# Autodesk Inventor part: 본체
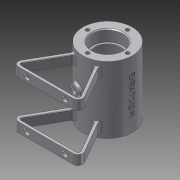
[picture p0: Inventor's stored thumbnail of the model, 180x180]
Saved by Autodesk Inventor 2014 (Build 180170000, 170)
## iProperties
Created: 2016-03
Part Number: 본체
Material: Aluminum 6061
Document SubType Name: Modeling
Designer: user
Density: 2.71 g/cm^3
Appearance: Aluminum - Flat
Mass: 209.602 g
Surface Area: 327.231 cm^2
Volume: 77.3441 cm^3
Author: user
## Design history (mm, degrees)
sketch "Sketch1"
  geometry: C1 r 26 at (0, 0); 1 further point
  constraints: 1 centre point, 1 coincident
  dimensions: "d0" = 52 diameter of C1
extrude "Extrusion1" new body sketch "Sketch1" distance "d1" = 35; taper "d2" = 0 deg
sketch "Sketch2"
  geometry: 4 further points
hole "Hole1" sketch "Sketch2" at (0, 21), (-21, 0), (0, -21), (21, 0) diameter "d5" = 4; stored, may be unused: countersink angle "d9" = 82 deg, drill point angle "d11" = 118 deg; dims "d6" = 5.984, "d7" = 3.023, "d8" = 2, "d10" = 8
sketch "Sketch3"
  geometry: C1 r 26 at (0, 0) reference; C2 r 16 at (0, 0)
  constraints: 1 centre point, 1 coincident
  dimensions: "d12" = 32 diameter of C2
extrude "Extrusion2" cut sketch "Sketch3" distance "d13" = 12; taper "d14" = 0 deg
sketch "Sketch4"
  geometry: C1 r 16 at (0, 0) reference; C2 r 14 at (0, 0)
  constraints: 1 centre point, 1 coincident
  dimensions: "d15" = 28 diameter of C2
extrude "Extrusion3" cut sketch "Sketch4" distance "d16" = 2; taper "d17" = 0 deg
sketch "Sketch5"
  geometry: C1 r 26 at (0, 0) reference; C2 r 21 at (0, 0)
  constraints: 1 centre point, 1 coincident
  dimensions: "d18" = 42 diameter of C2
extrude "Extrusion4" cut sketch "Sketch5" distance "d19" = 21; taper "d20" = 0 deg
fillet "Fillet1" dims "d21" = 0.3
workplane "Work Plane1"
sketch "Sketch6"
  geometry: L1 (13, -22.517)-(33.198, -57.5); L2 (28.868, -65)-(-28.868, -65); L3 (-33.198, -57.5)-(-13, -22.517); L4 (-28.868, -62)-(28.868, -62); L5 (30.6, -59)-(10.315, -23.866); L6 (-10.315, -23.866)-(-30.6, -59); A1 r 5 centre (28.868, -60) between (28.868, -65) and (33.198, -57.5); A2 r 5 centre (-28.868, -60) between (-33.198, -57.5) and (-28.868, -65); A3 r 2 centre (28.868, -60) between (28.868, -62) and (30.6, -59); A4 r 2 centre (-28.868, -60) between (-30.6, -59) and (-28.868, -62); A5 r 26 centre (0, 0) between (-13, -22.517) and (-10.315, -23.866); A6 r 26 centre (0, 0) between (10.315, -23.866) and (13, -22.517); 1 further point
  constraints: 12 end point, 12 point on circle, 6 centre point, 4 tangent, 1 coincident, 1 equal radius, 1 horizontal, 1 other
  dimensions: "d23" = 65 distance from line of L2 point (0, 0); "d24" = 60 deg angle of L2 L1; "d25" = 60 deg angle of L2 L3; "d26" = 5 radius of A1; "d27" = 3 distance between parallel lines of L2 L4
extrude "Extrusion5" join sketch "Sketch6" distance "d29" = 10; taper "d30" = 0 deg
sketch "Sketch7"
  geometry: L1 (57.735, 0)-(57.735, -10) reference; L2 (-20.076, -5)-(63.87, -5); L3 (28.868, 5.708)-(28.868, -22.708); C1 r 3 at (8.868, -5); C2 r 3 at (48.868, -5); 1 further point
  constraints: 4 end point, 2 centre point, 2 perpendicular, 1 point on line, 1 symmetric about line, 1 other
  dimensions: "d31" = 6 diameter of C1; "d32" = 40 diameter of C1.centre L3
extrude "Extrusion6" cut sketch "Sketch7" distance "d33" = 10; taper "d34" = 0 deg
fillet "Fillet2" dims "d35" = 3
fillet "Fillet3" dims "d36" = 0.5
fillet "Fillet4" dims "d37" = 3
chamfer "Chamfer1" distance "d38" = 1; stored, may be unused: second distance "d39" = 2, angle "d40" = 45 deg
mirror "Mirror1"
workplane "Work Plane2"
sketch "Sketch8"
  geometry: C1 r 5 at (0, 0); 1 further point
  constraints: 1 centre point, 1 coincident
  dimensions: "d42" = 10 diameter of C1
extrude "Extrusion7" join sketch "Sketch8" stored distance "d43" = 3; taper "d44" = 0 deg
fillet "Fillet5" dims "d45" = 2
sketch "Sketch9"
  geometry: A1 r 5 centre (0, 0) between (-3.763, 3.293) and (-3.763, -3.293) reference; A2 r 5 centre (0, 0) between (3.763, -3.293) and (3.763, 3.293) reference; 1 further point
  constraints: 1 coincident
hole "Hole2" sketch "Sketch9" at (0, 0) diameter "d46" = 6; stored, may be unused: countersink angle "d50" = 90 deg, drill point angle "d52" = 0 deg; dims "d47" = 5.984, "d48" = 12.6, "d49" = 2, "d51" = 10
workplane "Work Plane3"
workplane "Work Plane4"
sketch "Sketch10"
  geometry: L1 (37.027, 18.388)-(37.027, -18.909); L2 (37.027, -18.909)-(-37.914, -18.909); L3 (-37.914, -18.909)-(-37.914, 18.388); L4 (-37.914, 18.388)-(37.027, 18.388); 2 further points
  constraints: 1 coincident, 2 other
emboss "Emboss1" sketch "Sketch10" dims "d1" = 35, "d55" = 0.5, "d56" = 0
sketch "Sketch11"
  geometry: L1 (0, 0)-(-12.906, -48.164); L2 (0, 0)-(0, -50.645); L3 (-54.047, -12.43)-(49.71, -40.232)
  constraints: 6 end point, 1 perpendicular, 1 vertical
  dimensions: "d57" = 15 deg angle of L2 L1
workplane "Work Plane5"
sketch "Sketch12"
  geometry: C1 r 6 at (48.988, 0); 1 further point
  constraints: 1 centre point, 1 coincident
  dimensions: "d59" = 12 diameter of C1
extrude "Extrusion8" join sketch "Sketch12" stored distance "d60" = 6; taper "d61" = 0 deg
fillet "Fillet6" dims "d62" = 2
sketch "Sketch13"
  geometry: C1 r 6 at (0, 0) reference; 1 further point
  constraints: 1 coincident
hole "Hole3" sketch "Sketch13" at (0, 0) diameter "d63" = 6; stored, may be unused: countersink angle "d67" = 90 deg, drill point angle "d69" = 0 deg; dims "d64" = 5.984, "d65" = 12.6, "d66" = 2, "d68" = 20
body "Solid1"
other parameters: "d28" = 52, "d41" = 26, "d53" = -26, "d54" = 26, "d58" = 90 deg
